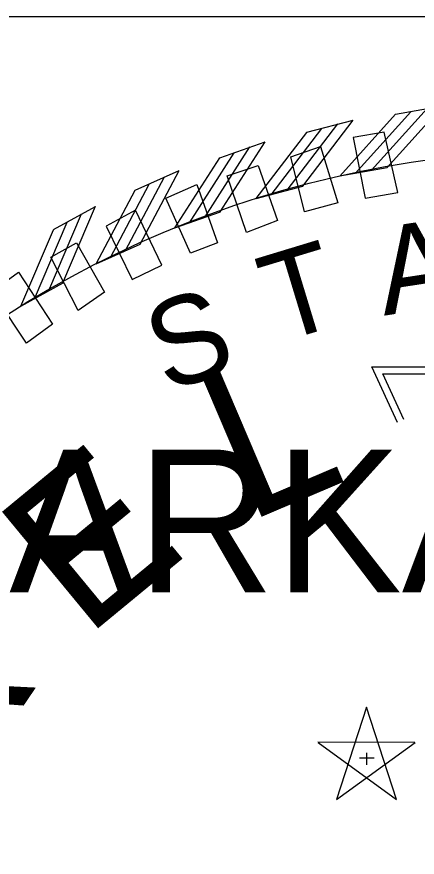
# Model space of a CAD drawing. Extents: x 16 to 1228740, y 11 to 152440.
# Drawn here: x 17.723 to 17.7544, y 10.9327 to 10.9986 of the extents above; entities that cross this region are included whole.
import ezdxf

# ---------------------------------------------------------------- set-up
doc = ezdxf.new("R2010")
doc.units = 0
for name, color, linetype in [('B_Preliminary', 7, 'Continuous'), ('B_StampERBB', 7, 'Continuous'), ('B_StampHSS', 7, 'Continuous'), ('B_StampJSB', 7, 'Continuous'), ('B_StampSCR', 7, 'Continuous'), ('B_StampSFH', 7, 'Continuous'), ('R_No Plot', 7, 'Continuous')]:
    doc.layers.add(name, color=color, linetype=linetype)

msp = doc.modelspace()

# ---------------------------------------------------------------- linework, layer by layer
at = {"layer": 'B_Preliminary'}
for p, q in [((17.751835, 10.989599), (17.749402, 10.989158)), ((17.752902, 10.984849), (17.751835, 10.989599)), ((17.749402, 10.989158), (17.750335, 10.984408)), ((17.744527, 10.987658), (17.746835, 10.988474)), ((17.746835, 10.988474), (17.74821, 10.984033)), ((17.745585, 10.983349), (17.744527, 10.987658)), ((17.739527, 10.986158), (17.74196, 10.986974)), ((17.74196, 10.986974), (17.74346, 10.982658)), ((17.741027, 10.981724), (17.739527, 10.986158)), ((17.73471, 10.984408), (17.737152, 10.985474)), ((17.737152, 10.985474), (17.738777, 10.980908)), ((17.750335, 10.984408), (17.752902, 10.984849)), ((17.736652, 10.980099), (17.73471, 10.984408)), ((17.74821, 10.984033), (17.745585, 10.983349)), ((17.732335, 10.983474), (17.730027, 10.982224)), ((17.734402, 10.979158), (17.732335, 10.983474)), ((17.74346, 10.982658), (17.741027, 10.981724)), ((17.730027, 10.982224), (17.732085, 10.978033)), ((17.72571, 10.979783), (17.72771, 10.980908)), ((17.72771, 10.980908), (17.729902, 10.977033)), ((17.738777, 10.980908), (17.736652, 10.980099)), ((17.727835, 10.975599), (17.72571, 10.979783)), ((17.732085, 10.978033), (17.734402, 10.979158)), ((17.721085, 10.977099), (17.723152, 10.978599)), ((17.723152, 10.978599), (17.725835, 10.974533)), ((17.723777, 10.973033), (17.721085, 10.977099)), ((17.729902, 10.977033), (17.727835, 10.975599)), ((17.725835, 10.974533), (17.723777, 10.973033))]:
    msp.add_line(p, q, dxfattribs=at)
at = {"layer": 'B_StampERBB'}
for p, q in [((17.752726, 10.990997), (17.756438, 10.991651)), ((17.745763, 10.989574), (17.749409, 10.990533)), ((17.738942, 10.987581), (17.742496, 10.988838)), ((17.732308, 10.985031), (17.735747, 10.986577)), ((17.748356, 10.986153), (17.752077, 10.986809)), ((17.741808, 10.984385), (17.745463, 10.985347)), ((17.725908, 10.981943), (17.729207, 10.983768)), ((17.735429, 10.982084), (17.738991, 10.983343)), ((17.729261, 10.979263), (17.732708, 10.980812)), ((17.723348, 10.975942), (17.726654, 10.977771)), ((17.750447, 10.944483), (17.748088, 10.937247)), ((17.752797, 10.937251), (17.750452, 10.944492)), ((17.754249, 10.941721), (17.746638, 10.941728)), ((17.746645, 10.941721), (17.752798, 10.937242)), ((17.748097, 10.937251), (17.754258, 10.941719)), ((17.749905, 10.940505), (17.751036, 10.940505)), ((17.750454, 10.940912), (17.750454, 10.939957))]:
    msp.add_line(p, q, dxfattribs=at)
for points in [[(17.749549, 10.986348), (17.753918, 10.991192)], [(17.750833, 10.986604), (17.755202, 10.991448)], [(17.752072, 10.986811), (17.756441, 10.991655)], [(17.745458, 10.985348), (17.749412, 10.990536)], [(17.748352, 10.986148), (17.752721, 10.990992)], [(17.742981, 10.984679), (17.746935, 10.989867)], [(17.74424, 10.98504), (17.748194, 10.990228)], [(17.741805, 10.984381), (17.745759, 10.989569)], [(17.738986, 10.983344), (17.742498, 10.988841)], [(17.736573, 10.982473), (17.740085, 10.98797)], [(17.737798, 10.982937), (17.74131, 10.988434)], [(17.735426, 10.982079), (17.738938, 10.987576)], [(17.732703, 10.980813), (17.735749, 10.986581)], [(17.731552, 10.980309), (17.734598, 10.986077)], [(17.73037, 10.979745), (17.733416, 10.985513)], [(17.729259, 10.979258), (17.732305, 10.985026)], [(17.726649, 10.977772), (17.729209, 10.983772)], [(17.725545, 10.977174), (17.728104, 10.983174)], [(17.723346, 10.975937), (17.725905, 10.981937)], [(17.724413, 10.976515), (17.726972, 10.982515)], [(17.752875, 10.966818), (17.750865, 10.97117), (17.785635, 10.97119), (17.78273, 10.96754), (17.785092, 10.967571), (17.787065, 10.967597), (17.789037, 10.967382)], [(17.753375, 10.967049), (17.751726, 10.97062), (17.784493, 10.970639), (17.781576, 10.966974), (17.785099, 10.96702), (17.787039, 10.967045), (17.788977, 10.966834)]]:
    msp.add_lwpolyline(points, dxfattribs=at)
at = {"layer": 'B_StampHSS'}
for p, q in [((17.752726, 10.990997), (17.756438, 10.991651)), ((17.745763, 10.989574), (17.749409, 10.990533)), ((17.738942, 10.987581), (17.742496, 10.988838)), ((17.732308, 10.985031), (17.735747, 10.986577)), ((17.748356, 10.986153), (17.752077, 10.986809)), ((17.741808, 10.984385), (17.745463, 10.985347)), ((17.725908, 10.981943), (17.729207, 10.983768)), ((17.735429, 10.982084), (17.738991, 10.983343)), ((17.729261, 10.979263), (17.732708, 10.980812)), ((17.723348, 10.975942), (17.726654, 10.977771)), ((17.750447, 10.944483), (17.748088, 10.937247)), ((17.752797, 10.937251), (17.750452, 10.944492)), ((17.754249, 10.941721), (17.746638, 10.941728)), ((17.746645, 10.941721), (17.752798, 10.937242)), ((17.748097, 10.937251), (17.754258, 10.941719)), ((17.749905, 10.940505), (17.751036, 10.940505)), ((17.750454, 10.940912), (17.750454, 10.939957))]:
    msp.add_line(p, q, dxfattribs=at)
for points in [[(17.749549, 10.986348), (17.753918, 10.991192)], [(17.750833, 10.986604), (17.755202, 10.991448)], [(17.752072, 10.986811), (17.756441, 10.991655)], [(17.745458, 10.985348), (17.749412, 10.990536)], [(17.748352, 10.986148), (17.752721, 10.990992)], [(17.742981, 10.984679), (17.746935, 10.989867)], [(17.74424, 10.98504), (17.748194, 10.990228)], [(17.741805, 10.984381), (17.745759, 10.989569)], [(17.738986, 10.983344), (17.742498, 10.988841)], [(17.736573, 10.982473), (17.740085, 10.98797)], [(17.737798, 10.982937), (17.74131, 10.988434)], [(17.735426, 10.982079), (17.738938, 10.987576)], [(17.732703, 10.980813), (17.735749, 10.986581)], [(17.731552, 10.980309), (17.734598, 10.986077)], [(17.73037, 10.979745), (17.733416, 10.985513)], [(17.729259, 10.979258), (17.732305, 10.985026)], [(17.726649, 10.977772), (17.729209, 10.983772)], [(17.725545, 10.977174), (17.728104, 10.983174)], [(17.723346, 10.975937), (17.725905, 10.981937)], [(17.724413, 10.976515), (17.726972, 10.982515)], [(17.752875, 10.966818), (17.750865, 10.97117), (17.785635, 10.97119), (17.78273, 10.96754), (17.785092, 10.967571), (17.787065, 10.967597), (17.789037, 10.967382)], [(17.753375, 10.967049), (17.751726, 10.97062), (17.784493, 10.970639), (17.781576, 10.966974), (17.785099, 10.96702), (17.787039, 10.967045), (17.788977, 10.966834)]]:
    msp.add_lwpolyline(points, dxfattribs=at)
at = {"layer": 'B_StampJSB'}
for p, q in [((17.752726, 10.990997), (17.756438, 10.991651)), ((17.745763, 10.989574), (17.749409, 10.990533)), ((17.738942, 10.987581), (17.742496, 10.988838)), ((17.732308, 10.985031), (17.735747, 10.986577)), ((17.748356, 10.986153), (17.752077, 10.986809)), ((17.741808, 10.984385), (17.745463, 10.985347)), ((17.725908, 10.981943), (17.729207, 10.983768)), ((17.735429, 10.982084), (17.738991, 10.983343)), ((17.729261, 10.979263), (17.732708, 10.980812)), ((17.723348, 10.975942), (17.726654, 10.977771)), ((17.750447, 10.944483), (17.748088, 10.937247)), ((17.752797, 10.937251), (17.750452, 10.944492)), ((17.754249, 10.941721), (17.746638, 10.941728)), ((17.746645, 10.941721), (17.752798, 10.937242)), ((17.748097, 10.937251), (17.754258, 10.941719)), ((17.749905, 10.940505), (17.751036, 10.940505)), ((17.750454, 10.940912), (17.750454, 10.939957))]:
    msp.add_line(p, q, dxfattribs=at)
for points in [[(17.749549, 10.986348), (17.753918, 10.991192)], [(17.750833, 10.986604), (17.755202, 10.991448)], [(17.752072, 10.986811), (17.756441, 10.991655)], [(17.745458, 10.985348), (17.749412, 10.990536)], [(17.748352, 10.986148), (17.752721, 10.990992)], [(17.742981, 10.984679), (17.746935, 10.989867)], [(17.74424, 10.98504), (17.748194, 10.990228)], [(17.741805, 10.984381), (17.745759, 10.989569)], [(17.738986, 10.983344), (17.742498, 10.988841)], [(17.736573, 10.982473), (17.740085, 10.98797)], [(17.737798, 10.982937), (17.74131, 10.988434)], [(17.735426, 10.982079), (17.738938, 10.987576)], [(17.732703, 10.980813), (17.735749, 10.986581)], [(17.731552, 10.980309), (17.734598, 10.986077)], [(17.73037, 10.979745), (17.733416, 10.985513)], [(17.729259, 10.979258), (17.732305, 10.985026)], [(17.726649, 10.977772), (17.729209, 10.983772)], [(17.725545, 10.977174), (17.728104, 10.983174)], [(17.723346, 10.975937), (17.725905, 10.981937)], [(17.724413, 10.976515), (17.726972, 10.982515)], [(17.752875, 10.966818), (17.750865, 10.97117), (17.785635, 10.97119), (17.78273, 10.96754), (17.785092, 10.967571), (17.787065, 10.967597), (17.789037, 10.967382)], [(17.753375, 10.967049), (17.751726, 10.97062), (17.784493, 10.970639), (17.781576, 10.966974), (17.785099, 10.96702), (17.787039, 10.967045), (17.788977, 10.966834)]]:
    msp.add_lwpolyline(points, dxfattribs=at)
msp.add_circle((17.766447, 10.906117), 0.082054, dxfattribs=at)
at = {"layer": 'B_StampSCR'}
for p, q in [((17.752726, 10.990997), (17.756438, 10.991651)), ((17.745763, 10.989574), (17.749409, 10.990533)), ((17.738942, 10.987581), (17.742496, 10.988838)), ((17.732308, 10.985031), (17.735747, 10.986577)), ((17.748356, 10.986153), (17.752077, 10.986809)), ((17.741808, 10.984385), (17.745463, 10.985347)), ((17.725908, 10.981943), (17.729207, 10.983768)), ((17.735429, 10.982084), (17.738991, 10.983343)), ((17.729261, 10.979263), (17.732708, 10.980812)), ((17.723348, 10.975942), (17.726654, 10.977771)), ((17.750447, 10.944483), (17.748088, 10.937247)), ((17.752797, 10.937251), (17.750452, 10.944492)), ((17.754249, 10.941721), (17.746638, 10.941728)), ((17.746645, 10.941721), (17.752798, 10.937242)), ((17.748097, 10.937251), (17.754258, 10.941719)), ((17.749905, 10.940505), (17.751036, 10.940505)), ((17.750454, 10.940912), (17.750454, 10.939957))]:
    msp.add_line(p, q, dxfattribs=at)
for points in [[(17.749549, 10.986348), (17.753918, 10.991192)], [(17.750833, 10.986604), (17.755202, 10.991448)], [(17.752072, 10.986811), (17.756441, 10.991655)], [(17.745458, 10.985348), (17.749412, 10.990536)], [(17.748352, 10.986148), (17.752721, 10.990992)], [(17.742981, 10.984679), (17.746935, 10.989867)], [(17.74424, 10.98504), (17.748194, 10.990228)], [(17.741805, 10.984381), (17.745759, 10.989569)], [(17.738986, 10.983344), (17.742498, 10.988841)], [(17.736573, 10.982473), (17.740085, 10.98797)], [(17.737798, 10.982937), (17.74131, 10.988434)], [(17.735426, 10.982079), (17.738938, 10.987576)], [(17.732703, 10.980813), (17.735749, 10.986581)], [(17.731552, 10.980309), (17.734598, 10.986077)], [(17.73037, 10.979745), (17.733416, 10.985513)], [(17.729259, 10.979258), (17.732305, 10.985026)], [(17.726649, 10.977772), (17.729209, 10.983772)], [(17.725545, 10.977174), (17.728104, 10.983174)], [(17.723346, 10.975937), (17.725905, 10.981937)], [(17.724413, 10.976515), (17.726972, 10.982515)], [(17.752875, 10.966818), (17.750865, 10.97117), (17.785635, 10.97119), (17.78273, 10.96754), (17.785092, 10.967571), (17.787065, 10.967597), (17.789037, 10.967382)], [(17.753375, 10.967049), (17.751726, 10.97062), (17.784493, 10.970639), (17.781576, 10.966974), (17.785099, 10.96702), (17.787039, 10.967045), (17.788977, 10.966834)]]:
    msp.add_lwpolyline(points, dxfattribs=at)
at = {"layer": 'B_StampSFH'}
for p, q in [((17.752726, 10.990997), (17.756438, 10.991651)), ((17.745763, 10.989574), (17.749409, 10.990533)), ((17.738942, 10.987581), (17.742496, 10.988838)), ((17.732308, 10.985031), (17.735747, 10.986577)), ((17.748356, 10.986153), (17.752077, 10.986809)), ((17.741808, 10.984385), (17.745463, 10.985347)), ((17.725908, 10.981943), (17.729207, 10.983768)), ((17.735429, 10.982084), (17.738991, 10.983343)), ((17.729261, 10.979263), (17.732708, 10.980812)), ((17.723348, 10.975942), (17.726654, 10.977771)), ((17.750447, 10.944483), (17.748088, 10.937247)), ((17.752797, 10.937251), (17.750452, 10.944492)), ((17.754249, 10.941721), (17.746638, 10.941728)), ((17.746645, 10.941721), (17.752798, 10.937242)), ((17.748097, 10.937251), (17.754258, 10.941719)), ((17.749905, 10.940505), (17.751036, 10.940505)), ((17.750454, 10.940912), (17.750454, 10.939957))]:
    msp.add_line(p, q, dxfattribs=at)
for points in [[(17.749549, 10.986348), (17.753918, 10.991192)], [(17.750833, 10.986604), (17.755202, 10.991448)], [(17.752072, 10.986811), (17.756441, 10.991655)], [(17.745458, 10.985348), (17.749412, 10.990536)], [(17.748352, 10.986148), (17.752721, 10.990992)], [(17.742981, 10.984679), (17.746935, 10.989867)], [(17.74424, 10.98504), (17.748194, 10.990228)], [(17.741805, 10.984381), (17.745759, 10.989569)], [(17.738986, 10.983344), (17.742498, 10.988841)], [(17.736573, 10.982473), (17.740085, 10.98797)], [(17.737798, 10.982937), (17.74131, 10.988434)], [(17.735426, 10.982079), (17.738938, 10.987576)], [(17.732703, 10.980813), (17.735749, 10.986581)], [(17.731552, 10.980309), (17.734598, 10.986077)], [(17.73037, 10.979745), (17.733416, 10.985513)], [(17.729259, 10.979258), (17.732305, 10.985026)], [(17.726649, 10.977772), (17.729209, 10.983772)], [(17.725545, 10.977174), (17.728104, 10.983174)], [(17.723346, 10.975937), (17.725905, 10.981937)], [(17.724413, 10.976515), (17.726972, 10.982515)], [(17.752875, 10.966818), (17.750865, 10.97117), (17.785635, 10.97119), (17.78273, 10.96754), (17.785092, 10.967571), (17.787065, 10.967597), (17.789037, 10.967382)], [(17.753375, 10.967049), (17.751726, 10.97062), (17.784493, 10.970639), (17.781576, 10.966974), (17.785099, 10.96702), (17.787039, 10.967045), (17.788977, 10.966834)]]:
    msp.add_lwpolyline(points, dxfattribs=at)
at = {"layer": 'R_No Plot'}
msp.add_line((17.887998, 10.998635), (17.47349, 10.998635), dxfattribs=at)

# ---------------------------------------------------------------- texts
at = {"layer": 'B_Preliminary'}
for s, rotation, p in [('L', 23.09236, (17.741027, 10.958908)), ('E', 39.5095, (17.728402, 10.949849)), ('R', 55.92663, (17.718527, 10.937158))]:
    msp.add_text(s, height=0.011841, rotation=rotation, dxfattribs=at).set_placement(p)
at = {"layer": 'B_StampERBB'}
for s, rotation, p in [('A', 8.67877, (17.751815, 10.975189)), ('T', 16.90148, (17.743487, 10.973014)), ('S', 19.77256, (17.734766, 10.969099))]:
    msp.add_text(s, height=0.006859, rotation=rotation, dxfattribs=at).set_placement(p)
msp.add_text('ARKANSAS', height=0.0111938, dxfattribs=at).set_placement((17.722443, 10.953498))
at = {"layer": 'B_StampHSS'}
for s, rotation, p in [('A', 8.67877, (17.751815, 10.975189)), ('T', 16.90148, (17.743487, 10.973014)), ('S', 19.77256, (17.734766, 10.969099))]:
    msp.add_text(s, height=0.006859, rotation=rotation, dxfattribs=at).set_placement(p)
msp.add_text('ARKANSAS', height=0.0111938, dxfattribs=at).set_placement((17.722443, 10.953498))
at = {"layer": 'B_StampJSB'}
for s, rotation, p in [('A', 8.67877, (17.751815, 10.975189)), ('T', 16.90148, (17.743487, 10.973014)), ('S', 19.77256, (17.734766, 10.969099))]:
    msp.add_text(s, height=0.006859, rotation=rotation, dxfattribs=at).set_placement(p)
msp.add_text('ARKANSAS', height=0.0111938, dxfattribs=at).set_placement((17.722443, 10.953498))
at = {"layer": 'B_StampSCR'}
for s, rotation, p in [('A', 8.67877, (17.751815, 10.975189)), ('T', 16.90148, (17.743487, 10.973014)), ('S', 19.77256, (17.734766, 10.969099))]:
    msp.add_text(s, height=0.006859, rotation=rotation, dxfattribs=at).set_placement(p)
msp.add_text('ARKANSAS', height=0.0111938, dxfattribs=at).set_placement((17.722443, 10.953498))
at = {"layer": 'B_StampSFH'}
for s, rotation, p in [('A', 8.67877, (17.751815, 10.975189)), ('T', 16.90148, (17.743487, 10.973014)), ('S', 19.77256, (17.734766, 10.969099))]:
    msp.add_text(s, height=0.006859, rotation=rotation, dxfattribs=at).set_placement(p)
msp.add_text('ARKANSAS', height=0.0111938, dxfattribs=at).set_placement((17.722443, 10.953498))

doc.saveas('drawing.dxf')
